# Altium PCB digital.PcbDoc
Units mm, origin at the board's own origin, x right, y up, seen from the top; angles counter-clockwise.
Board outline 150 x 30 mm, 2 copper layers (Top Layer, Bottom Layer); 64 components, 75 nets, 293 pads, 96 vias.
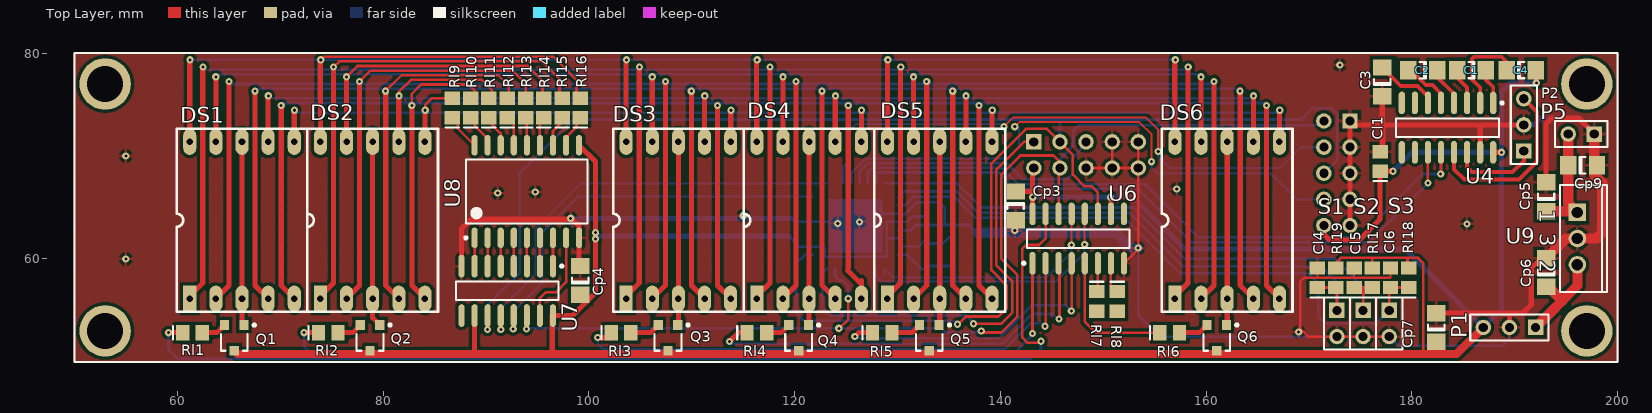
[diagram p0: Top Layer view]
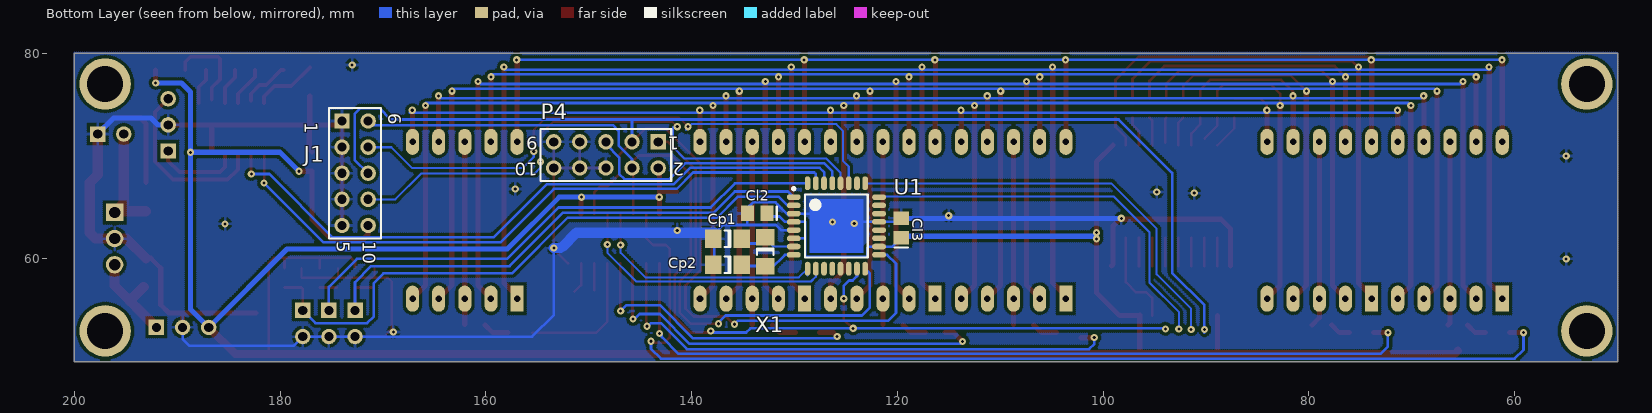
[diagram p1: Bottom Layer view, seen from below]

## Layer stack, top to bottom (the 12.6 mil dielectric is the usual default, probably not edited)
Top Layer: signal copper 0.0356
Dielectric: dielectric 0.32, FR-4, Dk 4.8
Bottom Layer: signal copper 0.0356

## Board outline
50,50 200,50 200,80 50,80

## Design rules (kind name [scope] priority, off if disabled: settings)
Clearance [All] p1: gap=0.2
ComponentClearance [All] p1 off: gap=0.254 collisioncheckmode=3 verticalgap=0.254
Height [All] p1 off: minheight=0 maxheight=25.4 prefheight=12.7
HoleSize [All] p1 off: absolutevalues=TRUE maxlimit=2.54 minlimit=0.025 maxpercent=80.000 minpercent=20.000
PolygonConnect [All] p1: connectstyle=Relief reliefconductorwidth=0.254 reliefentries=4 polygonreliefangle="90 Angle"
RoomDefinition cpu [InComponentClass('cpu')] p1 off: confinementstyle=ConfineIn formatcopy=TRUE lockcomponents=FALSE outline 201.168,49.276 218.694,49.276 218.694,62.992 201.168,62.992
RoomDefinition U_led [InComponentClass('U_led')] p2 off: confinementstyle=ConfineIn formatcopy=TRUE lockcomponents=FALSE outline 201.168,49.022 213.106,49.022 213.106,57.15 201.168,57.15
RoutingVias [All] p1: holewidth=0.2 width=0.7 viastyle="Through Hole" minholewidth=0.3 minwidth=0.7 maxholewidth=5 maxwidth=5
SolderMaskExpansion [All] p1: expansion=0.102
TestPointUsage [All] p1: valid=0 allowmultiple=FALSE
Testpoint [All] p1: side=15 testpointundercomponent=TRUE minsize=1.016 maxsize=2.54 preferedsize=1.524 minholesize=0 maxholesize=1.016 preferedholesize=0.813 testpointgrid=0.025 style=1023 order=0123456789
Width [All] p1: maxlimit=10 minlimit=0.2 preferedwidth=0.254
16 further rules are at their usual default settings.

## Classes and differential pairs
component class U_led: Cl1 Cl2 Cl3 Cl4 Cl5 Cl6 DS1 DS2 DS3 DS4 DS5 DS6 P3 Q1 Q2 Q3 Q4 Q5 Q6 Rl1 Rl2 Rl3 Rl4 Rl5 Rl6 Rl7 Rl8 Rl9 Rl10 Rl11 Rl12 Rl13 Rl14 Rl15 Rl16 Rl17 Rl18 Rl19 S1 S2 S3 U6 U7 U8
component class cpu: C1 C2 C3 C4 Cp1 Cp2 Cp3 Cp4 Cp5 Cp6 Cp7 Cp9 J1 P1 P2 P4 P5 U1 U4 U9 X1

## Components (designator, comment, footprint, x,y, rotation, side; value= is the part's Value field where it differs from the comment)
C1 "Cap Pol2" C1206 185.801,78.359 r180 top
C2 "Cap Pol2" C1206 181.052,78.348 r180 top
C3 "Cap Pol2" C1206 177.115,77.205 r90 top
C4 "Cap Pol2" C1206 190.627,78.359 r0 top
Cl1 "Cap" C0805 176.911,69.469 r90 top
Cl2 "Cap" C0805 133.629,64.418 r0 bottom
Cl3 "Cap" C0805 119.634,62.992 r90 bottom
Cl4 "Cap" C0805 170.815,58.166 r90 top
Cl5 "Cap" C0805 174.384,58.166 r90 top
Cl6 "Cap" C0805 177.927,58.166 r90 top
Cp1 "Cap" C1206 136.525,61.976 r0 bottom
Cp2 "Cap" C1206 136.525,59.436 r0 bottom
Cp3 "Cap" C1206 141.478,65.151 r270 top
Cp4 "Cap" C1206 99.187,57.912 r90 top
Cp5 "Cap" C1206 193.04,66.04 r90 top
Cp6 "Cap" C1206 193.04,58.674 r90 top
Cp7 "Cap" C1206 182.372,53.34 r90 top
Cp9 "Cap" C1206 196.596,69.088 r0 top
DS1 "Dpy Red-CA" DIP10_7SEG 59.944,54.864 r90 top
DS2 "Dpy Red-CA" DIP10_7SEG 72.644,54.864 r90 top
DS3 "Dpy Red-CA" DIP10_7SEG 102.362,54.864 r90 top
DS4 "Dpy Red-CA" DIP10_7SEG 115.062,54.864 r90 top locked
DS5 "Dpy Red-CA" DIP10_7SEG 127.762,54.864 r90 top locked
DS6 "Dpy Red-CA" DIP10_7SEG 155.702,54.864 r90 top
J1 "Header 5X2A" HDR2X5_CEN 173.99,73.406 r270 bottom
P1 "Header 3" HDR1X3 192.024,53.34 r180 top
P2 "Header 3" HDR1X3 190.881,70.485 r90 top
P4 "Header 5X2" HDR2X5 143.256,71.374 r0 bottom
P5 "Header 2" HDR1X2 197.739,72.136 r180 top
Q1 "BC856" SOT-23B 65.532,52.324 r180 top
Q2 "BC856" SOT-23B 78.74,52.324 r180 top
Q3 "BC856" SOT-23B 107.696,52.324 r180 top
Q4 "BC856" SOT-23B 120.396,52.324 r180 top
Q5 "BC856" SOT-23B 133.096,52.324 r180 top
Q6 "BC856" SOT-23B 161.036,52.324 r180 top
Rl1 "Res2" C0805 61.468,52.832 r0 top
Rl2 "Res2" C0805 74.676,52.832 r0 top
Rl3 "Res2" C0805 103.124,52.832 r0 top
Rl4 "Res2" C0805 116.332,52.832 r0 top
Rl5 "Res2" C0805 128.524,52.832 r0 top
Rl6 "Res2" C0805 156.464,52.832 r0 top
Rl7 "Res2" C0805 149.352,55.88 r270 top
Rl8 "Res2" C0805 151.384,55.88 r270 top
Rl9 "Res2" C0805 86.741,74.676 r90 top
Rl10 "Res2" C0805 88.519,74.676 r90 top
Rl11 "Res2" C0805 90.297,74.676 r90 top
Rl12 "Res2" C0805 92.075,74.676 r90 top
Rl13 "Res2" C0805 93.853,74.676 r90 top
Rl14 "Res2" C0805 95.631,74.676 r90 top
Rl15 "Res2" C0805 97.409,74.676 r90 top
Rl16 "Res2" C0805 99.187,74.676 r90 top
Rl17 "Res2" C0805 176.149,58.166 r90 top
Rl18 "Res2" C0805 179.705,58.166 r90 top
Rl19 "Res2" C0805 172.593,58.166 r90 top
S1 "Header 2" HDR1X2 172.72,54.991 r270 top
S2 "Header 2" HDR1X2 175.26,54.991 r270 top
S3 "Header 2" HDR1X2 177.8,54.991 r270 top
U1 "ATmega8-16AC" 32A_L 125.934,63.2 r180 bottom
U4 "MAX232ACSE" NSO16_N 183.465,72.76 r270 top
U6 "MC74HC595AD" 751B-05_N 147.574,61.976 r90 top
U7 "MC74HC595AD" 751B-05_N 92.075,56.896 r270 top
U8 "ULN2803LW" LW18_L 93.98,66.548 r90 top
U9 "L7805CV" TO220ABN 196.088,61.976 r270 top
X1 "8Mhz" C1206 132.842,60.706 r270 bottom

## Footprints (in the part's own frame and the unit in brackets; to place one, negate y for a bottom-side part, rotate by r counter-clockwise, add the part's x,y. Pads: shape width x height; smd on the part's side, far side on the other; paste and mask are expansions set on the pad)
32A_L [mm] "Thin QFP, 32-Leads, Body 7x7mm, Pitch 0.8mm, IPC High Density"
  oval 1.35x0.55 smd: 1(-4.15,2.8) 2(-4.15,2) 3(-4.15,1.2) 4(-4.15,0.4) 5(-4.15,-0.4) 6(-4.15,-1.2) 7(-4.15,-2) 8(-4.15,-2.8) 17(4.15,-2.8) 18(4.15,-2) 19(4.15,-1.2) 20(4.15,-0.4) 21(4.15,0.4) 22(4.15,1.2) 23(4.15,2) 24(4.15,2.8)
  oval 0.55x1.35 smd: 9(-2.8,-4.15) 10(-2,-4.15) 11(-1.2,-4.15) 12(-0.4,-4.15) 13(0.4,-4.15) 14(1.2,-4.15) 15(2,-4.15) 16(2.8,-4.15) 25(2.8,4.15) 26(2,4.15) 27(1.2,4.15) 28(0.4,4.15) 29(-0.4,4.15) 30(-1.2,4.15) 31(-2,4.15) 32(-2.8,4.15)
  silkscreen extent -4.28,-3.05 3.05,3.75, body extent -3.5,-3.5 3.5,3.5, height 1.2
751B-05_N [mm] "SOIC, 16-Leads, Body 9.9x3.9mm, Pitch 1.27mm, IPC Medium Density"
  oval 2.2x0.6 smd: 1(-2.4,4.445) 2(-2.4,3.175) 3(-2.4,1.905) 4(-2.4,0.635) 5(-2.4,-0.635) 6(-2.4,-1.905) 7(-2.4,-3.175) 8(-2.4,-4.445) 9(2.4,-4.445) 10(2.4,-3.175) 11(2.4,-1.905) 12(2.4,-0.635) 13(2.4,0.635) 14(2.4,1.905) 15(2.4,3.175) 16(2.4,4.445)
  silkscreen extent -2.52,-5 0.9,5.42, body extent -2,-5 2,5, height 1.75
C0805 [mm] "Chip Capacitor; Body 2.0 x 1.2 mm (LxW typ)"
  rect 1.3x1.5 smd: 1(-0.95,0) 2(0.95,0)
  silkscreen extent -1.9,-0.65 -1.9,0.65
C1206 [mm] "Chip Capacitor; Body 3.2 x 1.6 mm (LxW typ)"
  rect 1.6x1.8 smd: 1(-1.4,0) 2(1.4,0)
  silkscreen extent -0.3,-0.8 0.3,0.8
DIP10_7SEG [mm]
  oval 2.54x1.27 hole 0.635: 1(1.27,-6.35) 2(1.27,-3.81) 4(1.27,-8.89) 5(1.27,-11.43) 6(16.51,-6.35) 7(16.51,-8.89) 8(16.51,-11.43) 9(16.51,-3.81) 10(16.51,-1.27)
  rect 2.54x1.27 hole 0.635: 3(1.27,-1.27)
  silkscreen extent 0,-12.7 17.78,0
HDR1X2 [mm] "Connector; Header; 2 Position"
  rect 1.5x1.5 hole 0.9: 1(0,0)
  round 1.5 hole 0.9: 2(2.54,0)
  silkscreen extent -1.27,-1.27 3.81,1.27
HDR1X3 [mm] "Connector; Header; 3 Position"
  rect 1.5x1.5 hole 0.9: 1(0,0)
  round 1.5 hole 0.9: 2(2.54,0) 3(5.08,0)
  silkscreen extent -1.27,-1.27 6.35,1.27
HDR2X5 [mm] "Connector; Header; 5x2 Position"
  rect 1.5x1.5 hole 0.9: 1(0,0)
  round 1.5 hole 0.9: 2(0,2.54) 3(2.54,0) 4(2.54,2.54) 5(5.08,0) 6(5.08,2.54) 7(7.62,0) 8(7.62,2.54) 9(10.16,0) 10(10.16,2.54)
  silkscreen extent -1.27,-1.27 11.43,3.81
HDR2X5_CEN [mm] "Connector; Header; 5x2 Position"
  rect 1.5x1.5 hole 0.9: 1(0,0)
  round 1.5 hole 0.9: 2(2.54,0) 3(5.08,0) 4(7.62,0) 5(10.16,0) 6(0,2.54) 7(2.54,2.54) 8(5.08,2.54) 9(7.62,2.54) 10(10.16,2.54)
  silkscreen extent -1.27,-1.27 11.43,3.81
LW18_L [mm] "SOIC, 18-Leads, Body 11.6x7.5mm, Pitch 1.27mm, IPC High Density"
  oval 2x0.6 smd: 1(-4.5,5.08) 2(-4.5,3.81) 3(-4.5,2.54) 4(-4.5,1.27) 5(-4.5,0) 6(-4.5,-1.27) 7(-4.5,-2.54) 8(-4.5,-3.81) 9(-4.5,-5.08) 10(4.5,-5.08) 11(4.5,-3.81) 12(4.5,-2.54) 13(4.5,-1.27) 14(4.5,0) 15(4.5,1.27) 16(4.5,2.54) 17(4.5,3.81) 18(4.5,5.08)
  silkscreen extent -4.62,-5.9 3.1,6.05, body extent -3.8,-5.95 3.8,5.95, height 2.65
NSO16_N [mm] "SOIC, 16-Leads, Body 9.9x3.9mm, Pitch 1.27mm, IPC Medium Density"
  oval 2.2x0.6 smd: 1(-2.4,4.445) 2(-2.4,3.175) 3(-2.4,1.905) 4(-2.4,0.635) 5(-2.4,-0.635) 6(-2.4,-1.905) 7(-2.4,-3.175) 8(-2.4,-4.445) 9(2.4,-4.445) 10(2.4,-3.175) 11(2.4,-1.905) 12(2.4,-0.635) 13(2.4,0.635) 14(2.4,1.905) 15(2.4,3.175) 16(2.4,4.445)
  silkscreen extent -2.52,-5 0.9,5.42, body extent -1.95,-4.95 1.95,4.95, height 1.75
SOT-23B [mm] "SOT-23; 3 Leads; Body 3.0 x 2.6 mm, inc. leads (LxW max)"
  rect 0.9x0.95 smd: 1(-0.95,-1.25) 2(0.95,-1.25) 3(0,1.25)
  silkscreen extent -2.08,-1.37 1.3,1.25
TO220ABN [mm] "TO, Thru-Hole, Vertical, Heatsink Mounted; 3 In-Line Leads; Pitch 2.54 mm; Pin sequence 1, 3, 2"
  rect 1.7x1.7 hole 1.1: 1(-2.54,0)
  round 1.7 hole 1.1: 2(2.54,0) 3(0,0)
  silkscreen extent -5.2,-1.7 5.2,2.9

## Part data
C1 C2 C3 C4: "Polarized Capacitor (Axial)"
Cl1 Cl2 Cl3 Cl4 Cl5 Cl6 Cp1 Cp2 Cp3 Cp4 Cp5 Cp6 Cp7 Cp9: "Capacitor"
DS1 DS2 DS3 DS4 DS5 DS6: "7.62 mm Black Surface HER 7-Segment Display: CA, RH DP"
J1 P4: "Header, 5-Pin, Dual row"
P1 P2: "Header, 3-Pin"
P5 S1 S2 S3: "Header, 2-Pin"
Q1 Q2 Q3 Q4 Q5 Q6: library part PNP, "PNP Bipolar Transistor"
Rl1 Rl2 Rl3 Rl4 Rl5 Rl6 Rl7 Rl8 Rl9 Rl10 Rl11 Rl12 Rl13 Rl14 Rl15 Rl16 Rl17 Rl18 Rl19: "Resistor"
U1: library part ULN2803A, "Octal Peripheral Driver Array"
U4: "+5V Powered, Multi-Channel RS-232 Driver/Receiver"
U6 U7: "8-Bit Serial-Input/Serial or Prallel-Output Shift Register with Latched 3-State Outputs"
U8: "High-Voltage, High-Current Darlington Array"
U9: "Positive Voltage Regulator"
X1: library part XTAL, "Crystal Oscillator"

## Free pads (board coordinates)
  round 5 hole 3.5: 0(53,53) 0(53,77) 0(197,53) 0(197,77)

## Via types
v1: diameter 0.7, hole 0.3, Top Layer to Bottom Layer, 96 vias

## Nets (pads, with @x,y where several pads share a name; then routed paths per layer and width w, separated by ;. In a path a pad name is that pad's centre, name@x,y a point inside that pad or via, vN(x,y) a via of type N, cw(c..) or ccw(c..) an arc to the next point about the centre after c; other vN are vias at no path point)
A: Cl4.1 Rl19.1 S1.1 U1.1 | length 53.5
  Top Layer w0.254: Cl4.1@171.069,57.216 172.72,57.216 S1.1
  Bottom Layer w0.254: U1.1@130.5,66 U1.1 130.634,66.55 135.8,66.55 137.85,64.5 152.5,64.5 157.7,59.3 171.15,59.3 172.72,57.73 S1.1
A1: Q1.2 Rl1.2 | length 2
  Top Layer w0.5: Rl1.2@62.868,52.832 63.84,52.832 Q1.2
A2: Q2.2 Rl2.2 | length 2
  Top Layer w0.5: Rl2.2@76.076,52.832 77.048,52.832 Q2.2
A3: Q3.2 Rl3.2 | length 2.5
  Top Layer w0.5: Rl3.2@104.524,52.832 106.004,52.832 Q3.2
A4: Q4.2 Rl4.2 | length 2.5
  Top Layer w0.5: Rl4.2 118.704,52.832 Q4.2
A5: Q5.2 Rl5.2 | length 2.5
  Top Layer w0.5: Rl5.2@129.924,52.832 131.404,52.832 Q5.2
A6: Q6.2 Rl6.2 | length 2.5
  Top Layer w0.5: Rl6.2@157.864,52.832 159.344,52.832 Q6.2
A7: Rl7.2
A8: Rl8.2
B: Cl5.1 Rl17.1 S2.1 U1.32 | length 56.9
  Top Layer w0.254: Cl5.1@174.498,57.216 Rl17.1 ; S2.1 175.26,57.206
  Bottom Layer w0.254: U1.32 135.8,67.35 138.15,65 152.95,65 157.95,60 172.55,60 175.26,57.29 S2.1
CLK: J1.8 P4.3 U1.17 U6.11 U7.11 | length 168.1
  Top Layer w0.254: v1@135.771,53.729 135.979,53.729 136.65,54.4 139.827,54.4 140.6,55.173 140.6,57.427 139.125,58.902 139.125,69.275 142.5,72.65 144.52,72.65 147.05,70.12 147.05,68.2 148.2,67.05 148.9,67.05 149.479,66.471 U6.11
  Bottom Layer w0.254: v1@90.17,52.832 90.17,55.499 93.3,58.629 93.3,68.35 98.5,73.55 169.25,73.55 170.35,74.65 172.2,74.65 172.75,74.1 172.75,69.626 J1.8 ; U1.17 121,60.4 120.142,59.542 120.142,54.758 120.925,53.975 135.525,53.975 v1(135.85,53.65) ; P4.3 145.796,73.405
  other v1: 90.15,53.15
D1: U7.15 U8.8 | length 9.2
  Top Layer w0.25: U7.15 95.25,56.2 95.8,56.75 96.8,56.75 97.79,57.74 U8.8
D2: U7.1 U8.7 | length 2.8
  Top Layer w0.25: U7.1 U8.7
D3: U7.2 U8.6 | length 2.8
  Top Layer w0.25: U7.2 U8.6
D4: U7.3 U8.5 | length 2.8
  Top Layer w0.25: U7.3 U8.5
D5: U7.4 U8.4 | length 2.8
  Top Layer w0.25: U7.4 U8.4
D6: U7.5 U8.3 | length 2.8
  Top Layer w0.25: U7.5 U8.3
D7: U7.6 U8.2 | length 2.8
  Top Layer w0.25: U7.6 U8.2
D8: U7.7 U8.1 | length 2.8
  Top Layer w0.25: U7.7 U8.1
DIN: J1.6 P4.4 U1.15 U6.14 U7.14 | length 110.8
  Top Layer w0.254: v1@124.333,52.959 124.333,53.233 125.222,54.122 v1@125.222,55.88 ; v1@138.15,52.85 140.1,52.85 141.65,54.4 141.65,58.45 140.1,60 140.1,68.2 141.95,70.05 145.15,70.05 145.796,69.404 P4.4 145.669,68.707 U6.14
  Bottom Layer w0.254: v1@93.95,53.05 94.15,53.25 134.3,53.25 134.7,52.85 137.95,52.85 v1@138.15,53.05 ; U1.15 123.934,58.316 124.35,57.9 124.7,57.9 125.222,57.378 v1(125.222,56.134) ; P4.4 145.796,69.696 147.1,71 147.1,72.45 147.65,73 171.044,73 J1.6
  other v1: 138.15,53 93.95,53.2 124.3,53.25
ELE: J1.9 U1.28 | length 55.5
  Top Layer w0.2: v1(141.4,72.85) 141.85,73.3 153.5,73.3 154.7,72.1 v1(154.7,69.45)
  Bottom Layer w0.2: U1.28 125.534,68.384 126.9,69.75 140.7,69.75 141.8,70.85 141.8,72.8 ; v1(154.7,69.45) 154.7,68.85 155.25,68.3 166.3,68.3 168.814,65.786 J1.9
EOE: J1.7 U1.27 | length 56.6
  Top Layer w0.2: v1(140.35,72.85) 141.25,73.75 154.15,73.75 155.35,72.55 v1(155.35,70.45)
  Bottom Layer w0.2: U1.27 124.734,68.984 125.3,69.55 125.3,72.45 125.95,73.1 140,73.1 140.55,72.55 ; v1(155.35,70.45) 155.35,69.9 156.4,68.85 167.2,68.85 169.2,70.85 J1.7@171.05,70.85
GND: C3.1 Cl1.2 Cl2.2 Cl3.2 Cl4.2 Cl5.2 Cl6.2 Cp1.2 Cp2.2 Cp3.2 Cp4.2 Cp5.2 Cp6.2 Cp7.2 Cp9.2 J1.1 J1.2 J1.3 J1.4 J1.5 P1.2 P2.2 P4.6 P4.7 P4.8 P4.9 P4.10 P5.1 S1.2 S2.2 S3.2 U1.3 U1.5 U1.21 U4.15 U6.8 U7.8 U8.9 U9.3 | length 262.9
  Top Layer w0.2: 169.949,52.451 169.15,53.25 169.15,57.8 169.516,58.166 177.92,58.166 177.927,58.173 Cl6.2 ; 170.815,58.201 Cl4.2 ; 174.384,58.232 Cl5.2
  Top Layer w0.254: P4.6 P4.10 ; P4.8 P4.7 ; U6.8 153.416,60.973 P4.9 ; 169.949,52.451 S3.2
  Top Layer w0.5: U7.8 87.63,62.93 88.55,63.85 98.4,63.85 99.06,63.19 99.06,59.439 Cp4.2 ; Cl1.2 177.165,70.673 177.165,73.025 ; Cp7.2 190.79,54.74 191.6,55.55 191.6,59.1 192.574,60.074 Cp6.2 ; P1.2 189.484,54.706 ; Cp5.2 193.04,73.14 193.6,73.7 196.2,73.7 197.739,72.161 P5.1
  Top Layer w0.508: J1.5@173.99,63.125 J1.1@173.99,73.285 ; J1.1@174.065,73.025 P2.2 ; 177.115,73.025 C3.1 ; U4.15 186.64,72.965
  Top Layer w1: Cp6.2 194.942,61.976 197.926,61.976 198.5,62.55 198.5,67.4 197.739,68.161 P5.1
  Bottom Layer w0.254: Cl3.2 119.976,63.6 123.7,63.6 ; 128.1,64.4 U1.3@130.7,64.4 ; U1.5 131.3,62.8 131.8,63.3 136.972,63.3 137.922,62.35 141,62.35 v1(141.4,62.75) ; U1.3@130.575,64.225 131.85,65.5 134.05,65.5 134.6,64.95 134.6,63.3 ; Cp2.2@137.8,59.309 Cp1.2@137.8,62.55 ; v1(153.4,61.05) 153.4,54.55 155.499,52.451 S3.2 178.7,51.55 188.8,51.55 189.484,52.234 P1.2
  Bottom Layer w0.5: v1(98.237,63.942) Cl3.2
  Bottom Layer w0.508: P2.2 191.875,73.025 192.55,73.7 196.175,73.7 P5.1
  Bottom Layer w1: Cp1.2@137.8,62.55 151.2,62.55 152.6,61.15 ; 152.75,61.05 v1(153.4,61.05)
  other v1: 169,52.9 55,60 185.35,63.4 124.2,63.45 126.3,63.6 115.018,64.2 91.15,66.4 94.8,66.5 157.15,66.8 55,70 173,78.85
K1: DS1.10 DS2.10 DS3.10 DS4.10 DS5.10 DS6.10 Rl16.2 | length 171.3
  Top Layer w0.25: v1(73.95,79.35) 74.25,79.65 96.55,79.65 98.806,77.394 Rl16.2@98.806,75.626
  Top Layer w0.5: DS1.10 v1@61.214,79.314 ; v1@73.9,79.35 DS2.10 ; v1@103.618,79.35 DS3.10 ; v1@116.318,79.35 DS4.10 ; v1@129.018,79.35 DS5.10 ; v1@156.958,79.35 DS6.10
  Bottom Layer w0.25: v1(61.25,79.35) v1(157.008,79.35)
  other v1: 103.668,79.35 116.368,79.35 129.068,79.35
K2: DS1.9 DS2.9 DS3.9 DS4.9 DS5.9 DS6.9 Rl14.2 | length 157
  Top Layer w0.25: v1(76.45,77.7) 77.5,78.75 94.05,78.75 95.504,77.296 Rl14.2@95.504,75.626
  Top Layer w0.5: DS1.9 v1@63.754,77.7 ; DS2.9 v1@76.454,77.7 ; DS3.9 v1@106.172,77.7 ; DS4.9 v1@118.872,77.7 ; DS5.9 v1@131.572,77.7 ; DS6.9 v1@159.512,77.7
  Bottom Layer w0.25: v1(63.75,77.7) 64,77.95 v1@159.508,77.95 ; v1(76.45,77.7) 76.7,77.95 ; v1(106.168,77.7) 106.418,77.95 ; v1(118.868,77.7) 119.118,77.95 ; v1(131.568,77.7) 131.818,77.95
  other v1: 159.508,77.7
K3: DS1.8 DS2.8 DS3.8 DS4.8 DS5.8 DS6.8 Rl9.2 | length 120.9
  Top Layer w0.25: v1(84.1,74.45) 84.1,74.95 84.776,75.626 Rl9.2@87.249,75.626
  Top Layer w0.5: DS1.8 v1@71.374,74.218 ; DS2.8 v1@84.074,74.168 ; DS3.8 v1@113.792,74.168 ; DS4.8 v1@126.492,74.168 ; DS5.8 v1@139.192,74.168 ; v1@167.132,74.132 DS6.8 v1@167.132,74.168
  Bottom Layer w0.25: v1(71.4,74.45) 71.632,74.218 v1@167.1,74.218 ; v1(84.1,74.45) v1@84.332,74.218 ; v1(113.818,74.45) v1@114.05,74.218 ; v1(126.518,74.45) v1@126.75,74.218 ; v1(139.218,74.45) v1@139.45,74.218 ; v1(167.158,74.45) v1@167.39,74.218
K4: DS1.5 DS2.5 DS3.5 DS4.5 DS5.5 DS6.5 Rl10.2 | length 221.7
  Top Layer w0.25: v1@82.804,74.9 82.804,76.054 83.7,76.95 88.3,76.95 88.9,76.35 Rl10.2@88.9,75.626
  Top Layer w0.5: v1@70.104,74.9 70.104,57.404 DS1.5 ; v1@82.804,74.9 82.804,57.404 DS2.5 ; v1@112.522,74.93 112.522,57.404 DS3.5 ; 125.172,58.878 126.442,57.608 ; 125.222,59.178 v1@125.222,74.93 ; DS4.5 126.492,57.908 ; v1@137.922,74.93 137.922,57.404 DS5.5 ; v1@165.862,74.93 165.862,57.404 DS6.5
  Bottom Layer w0.25: v1(70.1,74.9) 70.35,75.15 v1@165.85,75.15 ; v1(82.8,74.9) 83.05,75.15 ; v1(112.518,74.9) 112.768,75.15 ; v1(125.218,74.9) 125.468,75.15 ; v1(137.918,74.9) 138.168,75.15
  other v1: 165.858,74.9
K5: DS1.4 DS2.4 DS3.4 DS4.4 DS5.4 DS6.4 Rl12.2 | length 236.4
  Top Layer w0.25: v1(80.25,76.3) 81.8,77.85 91.2,77.85 92.202,76.848 Rl12.2@92.202,75.626
  Top Layer w0.5: v1@67.564,76.3 67.564,57.404 DS1.4 ; v1@80.264,76.454 80.264,57.404 DS2.4 ; v1@109.982,76.454 109.982,57.404 DS3.4 ; v1@122.682,76.454 122.682,57.404 DS4.4 ; v1@135.382,76.454 135.382,57.404 DS5.4 ; v1@163.322,76.454 163.322,57.404 DS6.4
  Bottom Layer w0.25: v1(67.55,76.3) 67.8,76.55 v1@163.25,76.55 ; v1(80.25,76.3) 80.5,76.55 ; v1(109.968,76.3) 110.218,76.55 ; v1(122.668,76.3) 122.918,76.55 ; v1(135.368,76.3) 135.618,76.55
  other v1: 163.308,76.3
K6: DS1.2 DS2.2 DS3.2 DS4.2 DS5.2 DS6.2 Rl13.2 | length 245.6
  Top Layer w0.25: v1(77.724,77.25) 78.774,78.3 92.6,78.3 93.853,77.047 Rl13.2
  Top Layer w0.5: DS1.2 65.024,57.404 v1(65.024,77.25) ; DS2.2 77.724,57.404 v1@77.724,77.216 ; DS3.2 107.442,57.404 v1@107.442,77.216 ; DS4.2 120.142,57.404 v1@120.142,77.216 ; DS5.2 132.842,57.404 v1@132.842,77.216 ; DS6.2 160.782,57.404 v1@160.782,77.216
  Bottom Layer w0.25: v1(65.024,77.25) 65.274,77 160.5,77 v1@160.766,77.266 ; v1(77.724,77.25) 77.974,77 ; v1(107.442,77.25) 107.692,77 ; v1(120.142,77.25) 120.392,77 ; v1(132.842,77.25) 133.092,77
  other v1: 160.782,77.25
K7: DS1.3 DS2.3 DS3.3 DS4.3 DS5.3 DS6.3 Rl15.2 | length 257.8
  Top Layer w0.25: v1(75.2,78.65) 75.75,79.2 95.45,79.2 97.155,77.495 Rl15.2@97.155,75.626
  Top Layer w0.5: DS1.3@61.214,56.388 62.484,57.658 v1@62.484,78.74 ; DS2.3@73.914,56.388 75.184,57.658 v1@75.184,78.762 ; DS3.3@103.632,56.388 104.902,57.658 v1@104.902,78.74 ; DS4.3@116.332,56.388 117.602,57.658 v1@117.602,78.74 ; DS5.3@129.032,56.388 130.302,57.658 v1@130.302,78.74 ; DS6.3@156.972,56.388 158.242,57.658 v1@158.242,78.74
  Bottom Layer w0.25: v1@62.4,78.4 v1@158.158,78.4
  other v1: 62.5,78.65 104.918,78.65 117.618,78.65 130.318,78.65 158.258,78.65
K8: DS1.7 DS2.7 DS3.7 DS4.7 DS5.7 DS6.7 Rl11.2 | length 134.3
  Top Layer w0.25: v1(81.55,75.85) 81.55,76.25 82.7,77.4 89.6,77.4 90.551,76.449 Rl11.2@90.551,75.626
  Top Layer w0.5: DS1.7 v1@68.834,75.85 ; DS2.7 v1@81.534,75.692 ; DS3.7 v1@111.252,75.692 ; DS4.7 v1@123.952,75.692 ; DS5.7 v1@136.652,75.692 ; DS6.7 v1@164.592,75.692
  Bottom Layer w0.25: v1(68.85,75.85) 69.1,75.6 v1@164.5,75.6 ; v1(81.55,75.85) 81.8,75.6 ; v1(111.268,75.85) 111.518,75.6 ; v1(123.968,75.85) 124.218,75.6 ; v1(136.668,75.85) 136.918,75.6
  other v1: 164.608,75.85
LE: U1.25 U7.12 | length 41.3
  Bottom Layer w0.2: v1(91.45,53.15) 91.45,55.15 94.8,58.5 94.8,62.95 99.2,67.35 U1.25
LE2: U1.10 U6.12 | length 26.2
  Top Layer w0.2: v1(148.2,61.4) U6.12@148.2,64.367
  Bottom Layer w0.2: U1.10 127.934,58.266 128.4,57.8 145.4,57.8 148.2,60.6 v1(148.2,61.4)
MISO: P4.1 U1.16 | length 42.7
  Top Layer w0.254: v1@137.35,53.7 140.1,53.7 141.15,54.75 141.15,57.85 139.6,59.4 139.6,68.65 142.324,71.374 P4.1
  Bottom Layer w0.254: U1.16 122.682,58.598 122.682,55.268 123.45,54.5 136.7,54.5 v1@137.256,53.944
  other v1: 137.4,53.7
NetC1_1: C1.1 U4.1 | length 3.5
  Top Layer w0.381: C1.1 187.201,77.399 187.91,76.69 U4.1
NetC1_2: C1.2 U4.3 | length 3.6
  Top Layer w0.381: C1.2 184.401,77.649 185.37,76.68 U4.3
NetC2_1: C2.1 U4.4 | length 3.9
  Top Layer w0.381: C2.1 182.452,77.698 184.1,76.05 U4.4
NetC2_2: C2.2 U4.5 | length 4.8
  Top Layer w0.381: C2.2 179.902,78.348 181.35,76.9 182,76.9 182.85,76.05 U4.5@182.85,75.4
NetC3_2: C3.2 U4.6 | length 6.2
  Top Layer w0.381: C3.2 178.92,76.8 180.55,76.8 181.56,75.79 U4.6
NetC4_1: C4.1 U4.2 | length 8.7
  Top Layer w0.381: U4.2@186.65,75.5 186.65,76.65 185.85,77.45 185.85,79.45 186.05,79.65 188.7,79.65 189.227,79.123 C4.1
NetCp1_1: Cp1.1 U1.7 X1.1 | length 5.4
  Bottom Layer w0.2: U1.7 132.05,61.2 X1.1@132.75,61.9
  Bottom Layer w0.254: X1.1@132.842,61.5 134.395,61.5 Cp1.1@134.998,62.103
NetCp2_1: Cp2.1 U1.8 X1.2 | length 5.4
  Bottom Layer w0.254: U1.8 130.95,60.4 132.341,59.009 X1.2@132.792,59.009 ; X1.2@132.842,59.309 Cp2.1@134.998,59.309
NetCp5_1: Cp5.1 Cp9.1 P5.2 U9.1 | length 10.9
  Top Layer w1: Cp5.1 U9.1@195.964,64.64 ; P5.2 195.199,65.405 U9.1
NetCp6_1: Cp6.1 P1.1 U9.2 | length 9.9
  Top Layer w0.5: Cp6.1 Cp6.1@193.251,57.274 ; U9.2@196.1,59.05 196.287,59.237 U9.2@196.4,59.35
  Top Layer w1: P1.1 196.1,57.416 U9.2@196.1,59.05 ; Cp6.1@193.251,57.274 194.604,55.92
NetDS1_1: DS1.1 DS1.6 Q1.1 | length 17.9
  Top Layer w0.5: DS1.6 DS1.1 66.294,53.762 Q1.1
NetDS2_1: DS2.1 DS2.6 Q2.1 | length 18.1
  Top Layer w0.5: DS2.6 DS2.1 78.994,54.27 Q2.1
NetDS3_1: DS3.1 DS3.6 Q3.1 | length 17.7
  Top Layer w0.5: Q3.1@108.712,53.64 DS3.1 DS3.6
NetDS4_1: DS4.1 DS4.6 Q4.1 | length 17.7
  Top Layer w0.5: Q4.1@121.412,53.64 DS4.1 DS4.6
NetDS5_1: DS5.1 DS5.6 Q5.1 | length 17.7
  Top Layer w0.5: Q5.1@134.112,53.64 DS5.1 DS5.6
NetDS6_1: DS6.1 DS6.6 Q6.1 | length 17.7
  Top Layer w0.5: Q6.1@162.052,53.64 DS6.1 DS6.6
NetP2_1: P2.1 U4.14 | length 8.5
  Top Layer w0.381: U4.14 185.37,68.93 185.85,68.45 189.8,68.45 190.881,69.531 P2.1
NetP2_3: P2.3 U4.13 | length 17.5
  Top Layer w0.381: U4.13 184.1,68.7 185.1,67.7 190.4,67.7 192.15,69.45 192.15,74.296 P2.3
NetRl1_1: Rl1.1 U6.15 | length 105.2
  Top Layer w0.254: v1@143.95,51.85 142.65,51.85 142.15,52.35 142.15,61 142.5,61.35 143.75,61.35 144.399,61.999 U6.15
  Top Layer w0.5: v1@59.018,52.832 Rl1.1
  Bottom Layer w0.254: v1(59.15,52.832) 59.15,51.15 60,50.3 143,50.3 143.95,51.25 v1(143.95,52)
NetRl2_1: Rl2.1 U6.1 | length 81.5
  Top Layer w0.254: v1(143.129,52.75) U6.1
  Top Layer w0.5: v1(72.332,52.832) Rl2.1
  Bottom Layer w0.254: v1(72.332,52.832) 72.332,51.468 73.037,50.762 141.262,50.762 142.9,52.4 v1@142.9,52.75
NetRl3_1: Rl3.1 U6.2 | length 52.8
  Top Layer w0.254: v1@144.399,53.45 U6.2
  Top Layer w0.5: v1@100.868,52.332 Rl3.1@102.174,52.332
  Bottom Layer w0.254: v1(100.868,52.35) 100.868,51.732 101.375,51.225 140.475,51.225 143,53.75 143.95,53.75 v1@144.25,53.45
  other v1: 144.35,53.45
NetRl4_1: Rl4.1 U6.3 | length 41.1
  Top Layer w0.254: v1@145.75,54.15 U6.3@145.75,59.75
  Top Layer w0.5: v1(113.668,51.982) 114.518,52.832 Rl4.1
  Bottom Layer w0.254: v1(113.668,51.982) 113.9,51.75 140.2,51.75 143.1,54.65 145.05,54.65 v1@145.6,54.1
  other v1: 145.7,54.15
NetRl5_1: Rl5.1 U6.4 | length 29.1
  Top Layer w0.254: v1(146.9,54.95) 146.939,54.989 U6.4
  Top Layer w0.5: v1(125.857,52.451) 126.238,52.832 Rl5.1
  Bottom Layer w0.254: v1@125.857,52.3 139.9,52.3 143.1,55.5 146.35,55.5 v1(146.9,54.95)
NetRl6_1: Rl6.1 U6.5 | length 13.4
  Top Layer w0.254: U6.5 148.209,53.891 149.268,52.832 Rl6.1
NetRl7_1: Rl7.1 U6.6 | length 2.6
  Top Layer w0.254: Rl7.1@149.479,56.957 U6.6
NetRl8_1: Rl8.1 U6.7 | length 3
  Top Layer w0.254: U6.7 150.749,57.465 Rl8.1
NetRl9_1: Rl9.1 U8.18 | length 3.4
  Top Layer w0.25: Rl9.1@87.249,73.726 87.249,72.699 U8.18
NetRl10_1: Rl10.1 U8.17 | length 2.5
  Top Layer w0.25: Rl10.1@88.9,73.726 88.9,72.95 U8.17@90.15,71.7
NetRl11_1: Rl11.1 U8.16 | length 3
  Top Layer w0.25: Rl11.1@90.551,73.726 90.551,73.099 91.44,72.21 U8.16
NetRl12_1: Rl12.1 U8.15 | length 2.9
  Top Layer w0.25: Rl12.1@92.202,73.726 92.71,73.218 U8.15
NetRl13_1: Rl13.1 U8.14 | length 2.5
  Top Layer w0.25: Rl13.1 93.95,73.629 U8.14@93.95,71.3
NetRl14_1: Rl14.1 U8.13 | length 2.8
  Top Layer w0.25: U8.13 95.25,73.472 Rl14.1@95.504,73.726
NetRl15_1: Rl15.1 U8.12 | length 2.9
  Top Layer w0.25: U8.12 96.52,72.42 97.155,73.055 Rl15.1@97.155,73.726
NetRl16_1: Rl16.1 U8.11 | length 3.1
  Top Layer w0.25: U8.11 97.79,71.79 98.806,72.806 Rl16.1@98.806,73.726
OE: U1.24 U7.13 | length 38.3
  Bottom Layer w0.2: v1(92.65,53.2) 92.65,54.85 95.5,57.7 95.5,62.6 98.95,66.05 U1.24@121.784,66.05
OE2: U1.9 U6.13 | length 23.9
  Top Layer w0.2: v1(146.9,61.35) U6.13@146.9,64.337
  Bottom Layer w0.2: 128.734,58.366 U1.9 129.584,58.2 144.5,58.2 146.9,60.6 v1(146.9,61.35)
RST: P4.5 U1.29 | length 27
  Bottom Layer w0.25: U1.29 126.334,68.484 127.15,69.3 140.602,69.3 142.152,67.75 146.55,67.75 147.05,68.25 147.05,69.85 P4.5@148.3,71.1 ; U1.29@126.35,67.3 U1.29@126.35,67.85
RX: U1.30 U4.12 | length 64.3
  Top Layer w0.25: v1@182.83,68.28 U4.12
  Bottom Layer w0.25: U1.30 127.134,68.434 127.55,68.85 140.15,68.85 141.75,67.25 154.1,67.25 159.25,62.1 174.9,62.1 181.05,68.25 v1(182.8,68.25)
SW: Cl6.1 Rl18.1 S3.1 U1.2 | length 59.3
  Top Layer w0.254: S3.1 Cl6.1@177.8,57.089 ; Cl6.1 Rl18.1@179.578,57.216
  Bottom Layer w0.254: U1.2 130.7,65.2 131.55,66.05 135.5,66.05 137.55,64 152.05,64 157.45,58.6 169.95,58.6 170.9,57.65 170.9,54.4 171.55,53.75 176.559,53.75 S3.1
TX: U1.31 U4.11 | length 62.8
  Top Layer w0.25: v1@181.56,67.39 U4.11
  Bottom Layer w0.25: U1.31 127.934,68.234 128.1,68.4 139.85,68.4 141.45,66.8 153.4,66.8 158.6,61.6 175.8,61.6 v1(181.575,67.375)
VCC: C4.2 Cl1.1 Cl2.1 Cl3.1 Cp3.1 Cp4.1 Cp7.1 J1.10 P1.3 P4.2 Q1.3 Q2.3 Q3.3 Q4.3 Q5.3 Q6.3 Rl17.2 Rl18.2 Rl19.2 U1.4 U1.6 U1.18 U4.16 U6.10 U6.16 U7.10 U7.16 U8.10 | length 317.4
  Top Layer w0.254: Rl19.2@172.72,59.116 172.72,59.72 173.1,60.1 180.6,60.1 181.1,59.6 181.1,51.074 ; Rl17.2 176.149,59.999 ; Rl18.2@179.578,59.116 179.578,60.078
  Top Layer w0.5: 88.9,51.174 U7.10 ; 96.45,51.074 96.45,54.553 U7.16@96.456,54.559 ; U7.16@96.52,54.483 98.425,54.483 100.65,56.708 100.65,69.458 U8.10 ; Cp3.1 142.93,66.551 143.129,66.75 ; U6.16 143.129,68.707 P4.2 ; U6.10 150.749,65.5 ; J1.10 171.45,62.4 172,61.85 174.9,61.85 176.911,63.861 Cl1.1 v1(178.181,68.519) ; U4.16 v1(188.71,70.36) ; v1(192.1,77.1) C4.2@192.1,78.35
  Top Layer w0.8: Q1.3 65.856,50.75 184.354,50.75 P1.3
  Bottom Layer w0.254: Cl3.1@119.476,62.2 120.476,61.2 122.75,61.2 122.95,61 122.95,60.2 128.95,60.2 128.95,63.6 130.95,63.6 131.468,64.118 Cl2.1@132.629,64.118 ; 129,62 U1.6
  Bottom Layer w0.5: v1@100.65,62.4 100.85,62.2 Cl3.1@119.476,62.2 ; v1@143.45,66 152.866,66 157.916,60.95 179.334,60.95 P1.3 188.71,55.106 188.71,76.21 189.6,77.1 v1(192.1,77.1) ; v1(178.181,68.519) 180.022,70.36 v1(188.71,70.36)
  other v1: 100.65,61.95 100.65,62.55 143.15,66 150.7,66
pads on no net: U1.11 U1.12 U1.13 U1.14 U1.19 U1.20 U1.22 U1.23 U1.26 U4.7 U4.8 U4.9 U4.10 U6.9 U7.9

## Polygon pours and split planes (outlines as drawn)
GND on Top Layer "Bottom Layer-No Net" (hatched 90Degree grid 0.2 track 0.2): 50,80 200,80 200,50 50,50
GND on Bottom Layer "Bottom Layer-No Net" (hatched 90Degree grid 0.2 track 0.2): 50,80.074 50,50.074 200,50.074 200,80.074 50,80.074

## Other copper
Bottom Layer:
  rectangle net GND: 123.3,60.55 128.55,65.8

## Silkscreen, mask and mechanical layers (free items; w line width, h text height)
Top Overlay:
  the board outline again, w0.2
